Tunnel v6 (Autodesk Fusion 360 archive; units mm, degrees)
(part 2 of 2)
sketch "Sketch9" plane through (70, 0, 0) normal (1, 0, 0) x axis (0, 0, -1)
  line L1 (-4, 58) -> (-4, 62.9289)
  line L2 (-21, 58) -> (-4, 58)
  line L3 (-21, 62.9289) -> (-21, 58)
  line L4 (-25, 62.9289) -> (-21, 62.9289)
  line L5 (-25, 42.9289) -> (-25, 62.9289)
  line L6 (0, 42.9289) -> (-25, 42.9289)
  line L7 (0, 62.9289) -> (0, 42.9289)
  line L8 (-4, 62.9289) -> (0, 62.9289)
  line L9 (-4.1384, 55.5) -> (-21.17, 55.5)
  line L10 (-4.1384, 39.5) -> (-4.1384, 55.5)
  line L11 (-21.17, 39.5) -> (-4.1384, 39.5)
  line L12 (-21.17, 55.5) -> (-21.17, 39.5)
  line L13 (-34.0895, 0) -> (0, 0)
  line L14 (-39.8928, 0) -> (0, 0)
  line L15 (-4.1384, -55.5) -> (-21.17, -55.5)
  line L16 (-4.1384, -39.5) -> (-4.1384, -55.5)
  line L17 (-21.17, -55.5) -> (-21.17, -39.5)
  line L18 (-21.17, -39.5) -> (-4.1384, -39.5)
  point P1 (0, 0)
  point P16 (0, 0)
  point P10 (-21.17, 55.5)
  point P18 (-21.17, -55.5)
  point P11 (-4.1384, 55.5)
  point P19 (-4.1384, -55.5)
  point P12 (-4.1384, 39.5)
  point P20 (-4.1384, -39.5)
  point P13 (-21.17, 39.5)
  point P21 (-21.17, -39.5)
  horizontal L9
  vertical L10
  horizontal L11
  vertical L12
  coincident P1 P16
  parallel L13 L14
  symmetric P10 L14 P18
  symmetric P11 L14 P19
  symmetric P12 L14 P20
  symmetric P13 L14 P21
  dimension "d42" distance L2 L9 = 2.5
  dimension "d43" distance P10 P13 = 16
  dimension "d44" distance L11 L13 = 39.5
extrude "Extrude9" cut sketch "Sketch9" profile of L6 L9 L10 L11 L12 L15 L16 L17 L18 against normal blind 15
sketch "Sketch10" plane through (0, 0, 0) normal (0, 0, -1) x axis (-1, 0, 0)
  line L1 (-65, -40.0422) -> (-70, -28.9289)
  line L2 (-70, -42.9289) -> (-65, -40.0422)
  line L3 (-70, -62.9289) -> (-70, -42.9289)
  line L4 (-62.9289, -70) -> (-70, -62.9289)
  line L5 (-42.9289, -70) -> (-62.9289, -70)
  line L6 (-40.0422, -65) -> (-42.9289, -70)
  line L7 (-28.9289, -70) -> (-40.0422, -65)
  line L8 (28.9289, -70) -> (-28.9289, -70)
  line L9 (40.0422, -65) -> (28.9289, -70)
  line L10 (42.9289, -70) -> (40.0422, -65)
  line L11 (62.9289, -70) -> (42.9289, -70)
  line L12 (70, -62.9289) -> (62.9289, -70)
  line L13 (70, -42.9289) -> (70, -62.9289)
  line L14 (65, -40.0422) -> (70, -42.9289)
  line L15 (70, -28.9289) -> (65, -40.0422)
  line L16 (70, 28.9289) -> (70, -28.9289)
  line L17 (65, 40.0422) -> (70, 28.9289)
  line L18 (70, 42.9289) -> (65, 40.0422)
  line L19 (70, 62.9289) -> (70, 42.9289)
  line L20 (62.9289, 70) -> (70, 62.9289)
  line L21 (42.9289, 70) -> (62.9289, 70)
  line L22 (40.0422, 65) -> (42.9289, 70)
  line L23 (28.9289, 70) -> (40.0422, 65)
  line L24 (-28.9289, 70) -> (28.9289, 70)
  line L25 (-40.0422, 65) -> (-28.9289, 70)
  line L26 (-42.9289, 70) -> (-40.0422, 65)
  line L27 (-62.9289, 70) -> (-42.9289, 70)
  line L28 (-70, 62.9289) -> (-62.9289, 70)
  line L29 (-70, 42.9289) -> (-70, 62.9289)
  line L30 (-65, 40.0422) -> (-70, 42.9289)
  line L31 (-70, 28.9289) -> (-65, 40.0422)
  line L32 (-70, -28.9289) -> (-70, 28.9289)
  line L33 (66.4645, 66.4645) -> (0, 0)
  line L34 (0, 0) -> (-66.4645, 66.4645)
  line L35 (-44.063, 51.1341) -> (-10.8867, 17.9577)
  line L36 (-51.1341, 44.063) -> (-17.9577, 10.8867)
  line L37 (-52.5483, 45.4773) -> (-51.1341, 44.063)
  line L38 (-45.4773, 52.5483) -> (-52.5483, 45.4773)
  line L39 (-44.063, 51.1341) -> (-45.4773, 52.5483)
  line L40 (-51.1341, -44.063) -> (-17.9577, -10.8867)
  line L41 (-44.063, -51.1341) -> (-10.8867, -17.9577)
  line L42 (-52.5483, -45.4773) -> (-45.4773, -52.5483)
  line L43 (-51.1341, -44.063) -> (-52.5483, -45.4773)
  line L44 (-45.4773, -52.5483) -> (-44.063, -51.1341)
  line L45 (44.063, -51.1341) -> (10.8867, -17.9577)
  line L46 (51.1341, -44.063) -> (17.9577, -10.8867)
  line L47 (45.4773, -52.5483) -> (52.5483, -45.4773)
  line L48 (44.063, -51.1341) -> (45.4773, -52.5483)
  line L49 (52.5483, -45.4773) -> (51.1341, -44.063)
  line L50 (51.1341, 44.063) -> (17.9577, 10.8867)
  line L51 (44.063, 51.1341) -> (10.8867, 17.9577)
  line L52 (52.5483, 45.4773) -> (45.4773, 52.5483)
  line L53 (51.1341, 44.063) -> (52.5483, 45.4773)
  line L54 (45.4773, 52.5483) -> (44.063, 51.1341)
  circle C1 centre (-61.8683, 61.8683) radius 2.5
  circle C2 centre (61.8683, -61.8683) radius 2.5
  circle C3 centre (61.8683, 61.8683) radius 2.5
  circle C4 centre (-61.8683, -61.8683) radius 2.5
  circle C5 centre (0, 0) radius 67.5
  arc A1 centre (0, 0) radius 21 clockwise from (-10.8867, 17.9577) to (10.8867, 17.9577)
  arc A2 centre (0, 0) radius 21 clockwise from (-17.9577, -10.8867) to (-17.9577, 10.8867)
  arc A3 centre (0, 0) radius 21 clockwise from (10.8867, -17.9577) to (-10.8867, -17.9577)
  arc A4 centre (0, 0) radius 21 clockwise from (17.9577, 10.8867) to (17.9577, -10.8867)
  point P1 (0, 0)
  point P40 (0, 0)
  point P41 (66.4645, 66.4645)
  point P42 (-66.4645, 66.4645)
  point P44 (-44.063, 51.1341)
  point P46 (-51.1341, 44.063)
  point P47 (-52.5483, 45.4773)
  point P48 (-45.4773, 52.5483)
  concentric C5 A2
  coincident P1 P40
  midpoint L20 P41
  midpoint L28 P42
  coincident C5 P44
  perpendicular L33 L35
  coincident C5 P46
  parallel L34 L36
  symmetric L34 L35 L36
  parallel L36 L37
  perpendicular L34 L38
  concentric A1 A2
  concentric A2 A3
  concentric A3 A4
  dimension "d47" diameter A2 = 42
  dimension "d48" distance L35 L36 = 10
  dimension "d49" distance P47 P48 = 10
  dimension "d50" distance P44 P48 = 2
  dimension "d52" C-Pattern1-Angle = 360
extrude "Extrude10" add sketch "Sketch10" profile of C5 A4 L35 L36 L37 L38 L39 L40 L41 L42 L43 L44 L45 L46 L47 L48 L49 L50 L51 L52 L53 L54 against normal blind 3
fillet "Fillet1" radius 4
chamfer "Chamfer1" distance 3 distance 3 distance 3 distance 3
fillet "Fillet2" radius 1
fillet "Fillet3" radius 1.5
sketch "Sketch11" plane through (0, 0, 0) normal (0, 0, -1) x axis (-1, 0, 0)
  line L1 (-28.9289, 70) -> (-8.3815, 70)
  line L2 (-40.0422, 65) -> (-28.9289, 70)
  line L3 (-42.9289, 70) -> (-40.0422, 65)
  line L4 (-62.9289, 70) -> (-42.9289, 70)
  line L5 (-70, 62.9289) -> (-62.9289, 70)
  line L6 (-70, 42.9289) -> (-70, 62.9289)
  line L7 (-65, 40.0422) -> (-70, 42.9289)
  line L8 (-70, 28.9289) -> (-65, 40.0422)
  line L9 (-70, 8.3815) -> (-70, 28.9289)
  line L10 (-17.1164, 12.1667) -> (-52.2644, 47.3147)
  line L11 (-52.2644, -47.3147) -> (-17.1164, -12.1667)
  line L12 (-70, -28.9289) -> (-70, -8.3815)
  line L13 (-65, -40.0422) -> (-70, -28.9289)
  line L14 (-70, -42.9289) -> (-65, -40.0422)
  line L15 (-70, -62.9289) -> (-70, -42.9289)
  line L16 (-62.9289, -70) -> (-70, -62.9289)
  line L17 (-42.9289, -70) -> (-62.9289, -70)
  line L18 (-40.0422, -65) -> (-42.9289, -70)
  line L19 (-28.9289, -70) -> (-40.0422, -65)
  line L20 (-8.3815, -70) -> (-28.9289, -70)
  line L21 (-12.1667, -17.1164) -> (-47.3147, -52.2644)
  line L22 (47.3147, -52.2644) -> (12.1667, -17.1164)
  line L23 (28.9289, -70) -> (8.3815, -70)
  line L24 (40.0422, -65) -> (28.9289, -70)
  line L25 (42.9289, -70) -> (40.0422, -65)
  line L26 (62.9289, -70) -> (42.9289, -70)
  line L27 (70, -62.9289) -> (62.9289, -70)
  line L28 (70, -42.9289) -> (70, -62.9289)
  line L29 (65, -40.0422) -> (70, -42.9289)
  line L30 (70, -28.9289) -> (65, -40.0422)
  line L31 (70, -8.3815) -> (70, -28.9289)
  line L32 (17.1164, -12.1667) -> (52.2644, -47.3147)
  line L33 (52.2644, 47.3147) -> (17.1164, 12.1667)
  line L34 (70, 28.9289) -> (70, 8.3815)
  line L35 (65, 40.0422) -> (70, 28.9289)
  line L36 (70, 42.9289) -> (65, 40.0422)
  line L37 (70, 62.9289) -> (70, 42.9289)
  line L38 (62.9289, 70) -> (70, 62.9289)
  line L39 (42.9289, 70) -> (62.9289, 70)
  line L40 (40.0422, 65) -> (42.9289, 70)
  line L41 (28.9289, 70) -> (40.0422, 65)
  line L42 (8.3815, 70) -> (28.9289, 70)
  line L43 (12.1667, 17.1164) -> (47.3147, 52.2644)
  line L44 (-47.3147, 52.2644) -> (-12.1667, 17.1164)
  line L45 (-51.4652, 51.4652) -> (0, 0)
  line L46 (-47.5719, 50.4004) -> (-50.4004, 47.5719)
  line L47 (-13.6308, 16.4592) -> (-47.5719, 50.4004)
  line L48 (-16.4592, 13.6308) -> (-13.6308, 16.4592)
  line L49 (-50.4004, 47.5719) -> (-16.4592, 13.6308)
  line L50 (-16.4592, -13.6308) -> (-50.4004, -47.5719)
  line L51 (-47.5719, -50.4004) -> (-13.6308, -16.4592)
  line L52 (-50.4004, -47.5719) -> (-47.5719, -50.4004)
  line L53 (-13.6308, -16.4592) -> (-16.4592, -13.6308)
  line L54 (13.6308, -16.4592) -> (47.5719, -50.4004)
  line L55 (50.4004, -47.5719) -> (16.4592, -13.6308)
  line L56 (47.5719, -50.4004) -> (50.4004, -47.5719)
  line L57 (16.4592, -13.6308) -> (13.6308, -16.4592)
  line L58 (16.4592, 13.6308) -> (50.4004, 47.5719)
  line L59 (47.5719, 50.4004) -> (13.6308, 16.4592)
  line L60 (50.4004, 47.5719) -> (47.5719, 50.4004)
  line L61 (13.6308, 16.4592) -> (16.4592, 13.6308)
  arc A1 centre (0, 0) radius 70.5 clockwise from (-47.3147, 52.2644) to (-8.3815, 70)
  arc A2 centre (0, 0) radius 70.5 clockwise from (-70, 8.3815) to (-52.2644, 47.3147)
  arc A3 centre (0, 0) radius 21 clockwise from (-17.1164, -12.1667) to (-17.1164, 12.1667)
  arc A4 centre (0, 0) radius 70.5 clockwise from (-52.2644, -47.3147) to (-70, -8.3815)
  arc A5 centre (0, 0) radius 70.5 clockwise from (-8.3815, -70) to (-47.3147, -52.2644)
  arc A6 centre (0, 0) radius 21 clockwise from (12.1667, -17.1164) to (-12.1667, -17.1164)
  arc A7 centre (0, 0) radius 70.5 clockwise from (47.3147, -52.2644) to (8.3815, -70)
  arc A8 centre (0, 0) radius 70.5 clockwise from (70, -8.3815) to (52.2644, -47.3147)
  arc A9 centre (0, 0) radius 21 clockwise from (17.1164, 12.1667) to (17.1164, -12.1667)
  arc A10 centre (0, 0) radius 70.5 clockwise from (52.2644, 47.3147) to (70, 8.3815)
  arc A11 centre (0, 0) radius 70.5 clockwise from (8.3815, 70) to (47.3147, 52.2644)
  arc A12 centre (0, 0) radius 21 clockwise from (-12.1667, 17.1164) to (12.1667, 17.1164)
  circle C1 centre (-61.8683, -61.8683) radius 2.5
  circle C2 centre (61.8683, 61.8683) radius 2.5
  circle C3 centre (61.8683, -61.8683) radius 2.5
  circle C4 centre (-61.8683, 61.8683) radius 2.5
  point P4 (0, 0)
  point P63 (0, 0)
  point P66 (-47.5719, 50.4004)
  point P67 (-13.6308, 16.4592)
  coincident P4 P63
  parallel L44 L45
  perpendicular L45 L46
  perpendicular L46 L47
  perpendicular L10 L48
  parallel L47 L49
  dimension "d65" distance L47 L49 = 4
  dimension "d66" distance P66 P67 = 48
  dimension "d67" distance L45 L47 = 2
  dimension "d69" C-Pattern1-Angle = 360
extrude "Extrude11" cut sketch "Sketch11" profile of L46 L47 L48 L49 L50 L51 L52 L53 L54 L55 L56 L57 L58 L59 L60 L61 against normal blind 2
sketch "Sketch12" plane through (0, 70, 0) normal (0, 1, 0) x axis (-1, 0, 0)
  line L1 (62.9289, 21) -> (55, 21)
  line L2 (62.9289, 25) -> (62.9289, 21)
  line L3 (42.9289, 25) -> (62.9289, 25)
  line L4 (42.9289, 0) -> (42.9289, 25)
  line L5 (62.9289, 0) -> (42.9289, 0)
  line L6 (62.9289, 4) -> (62.9289, 0)
  line L7 (55, 4) -> (62.9289, 4)
  line L8 (55, 21) -> (55, 4)
  line L9 (0, 12.5) -> (55, 12.5)
  line L10 (37, 4.5) -> (53, 4.5)
  line L11 (37, 20.5) -> (37, 4.5)
  line L12 (53, 20.5) -> (37, 20.5)
  line L13 (53, 4.5) -> (53, 20.5)
  line L14 (0, 34.7836) -> (0, 0)
  line L15 (0, 34.7836) -> (0, 0)
  line L16 (-37, 4.5) -> (-53, 4.5)
  line L17 (-53, 4.5) -> (-53, 20.5)
  line L18 (-53, 20.5) -> (-37, 20.5)
  line L19 (-37, 20.5) -> (-37, 4.5)
  point P10 (55, 12.5)
  point P1 (0, 0)
  point P16 (0, 0)
  point P12 (53, 4.5)
  point P20 (-53, 4.5)
  point P13 (37, 4.5)
  point P21 (-37, 4.5)
  point P14 (37, 20.5)
  point P23 (-37, 20.5)
  point P15 (53, 20.5)
  point P22 (-53, 20.5)
  point P18 (0, 0)
  point P17 (0, 34.7836)
  point P19 (0, 34.7836)
  midpoint L8 P10
  perpendicular L8 L9
  horizontal L10
  vertical L11
  horizontal L12
  vertical L13
  symmetric L9 L10 L12
  coincident P1 P16
  perpendicular L10 L14
  symmetric P12 L14 P20
  symmetric P13 L14 P21
  symmetric P14 L14 P23
  symmetric P15 L14 P22
  symmetric P16 L14 P18
  symmetric P17 L14 P19
  dimension "d72" distance L8 L13 = 2
  dimension "d73" distance L11 L13 = 16
  dimension "d74" distance L10 L12 = 16
extrude "Extrude12" cut sketch "Sketch12" profile of L4 L10 L11 L12 L13 L16 L17 L18 L19 against normal blind 12
sketch "Sketch13" plane through (0, -70, 0) normal (0, -1, 0) x axis (1, 0, 0)
  line L1 (-62.9289, 4) -> (-55, 4)
  line L2 (-62.9289, 0) -> (-62.9289, 4)
  line L3 (-42.9289, 0) -> (-62.9289, 0)
  line L4 (-42.9289, 25) -> (-42.9289, 0)
  line L5 (-62.9289, 25) -> (-42.9289, 25)
  line L6 (-62.9289, 21) -> (-62.9289, 25)
  line L7 (-55, 21) -> (-62.9289, 21)
  line L8 (-55, 4) -> (-55, 21)
  line L9 (0.7063, 12.5) -> (-42.9289, 12.5)
  line L10 (-37, 20.5) -> (-53, 20.5)
  line L11 (-37, 4.5) -> (-37, 20.5)
  line L12 (-53, 4.5) -> (-37, 4.5)
  line L13 (-53, 20.5) -> (-53, 4.5)
  line L14 (0, 32.9134) -> (0, 0)
  line L15 (53, 20.5) -> (53, 4.5)
  line L16 (37, 20.5) -> (53, 20.5)
  line L17 (53, 4.5) -> (37, 4.5)
  line L18 (37, 4.5) -> (37, 20.5)
  point P10 (-42.9289, 12.5)
  point P1 (0, 0)
  point P16 (0, 0)
  point P12 (-53, 20.5)
  point P19 (53, 20.5)
  point P13 (-37, 20.5)
  point P20 (37, 20.5)
  point P14 (-37, 4.5)
  point P21 (37, 4.5)
  point P15 (-53, 4.5)
  point P18 (53, 4.5)
  midpoint L4 P10
  perpendicular L4 L9
  horizontal L10
  vertical L11
  horizontal L12
  vertical L13
  symmetric L9 L10 L12
  coincident P1 P16
  vertical L14
  symmetric P12 L14 P19
  symmetric P13 L14 P20
  symmetric P14 L14 P21
  symmetric P15 L14 P18
  dimension "d77" distance L8 L13 = 2
  dimension "d78" distance L11 L13 = 16
  dimension "d79" distance L10 L12 = 16
extrude "Extrude13" cut sketch "Sketch13" profile of L4 L10 L11 L12 L13 L15 L16 L17 L18 against normal blind 10
chamfer "Chamfer2" distance 2 distance 2 distance 2
chamfer "Chamfer3" distance 2
chamfer "Chamfer4" distance 2
chamfer "Chamfer5" distance 2
chamfer "Chamfer6" distance 2
sketch "Sketch14" plane through (0, 0, 3) normal (0, 0, 1) x axis (1, 0, 0)
  line L1 (11.749, 17.4058) -> (44.8174, 50.4743)
  line L2 (-44.8174, 50.4743) -> (-11.749, 17.4058)
  line L3 (-17.4058, 11.749) -> (-50.4743, 44.8174)
  line L4 (-50.4743, -44.8174) -> (-17.4058, -11.749)
  line L5 (-11.749, -17.4058) -> (-44.8174, -50.4743)
  line L6 (44.8174, -50.4743) -> (11.749, -17.4058)
  line L7 (17.4058, -11.749) -> (50.4743, -44.8174)
  line L8 (50.4743, 44.8174) -> (17.4058, 11.749)
  arc A1 centre (0, 0) radius 21 clockwise from (-11.749, 17.4058) to (11.749, 17.4058)
  arc A2 centre (0, 0) radius 67.5 clockwise from (-50.4743, 44.8174) to (-44.8174, 50.4743)
  arc A3 centre (0, 0) radius 21 clockwise from (-17.4058, -11.749) to (-17.4058, 11.749)
  arc A4 centre (0, 0) radius 67.5 clockwise from (-44.8174, -50.4743) to (-50.4743, -44.8174)
  arc A5 centre (0, 0) radius 21 clockwise from (11.749, -17.4058) to (-11.749, -17.4058)
  arc A6 centre (0, 0) radius 67.5 clockwise from (50.4743, -44.8174) to (44.8174, -50.4743)
  arc A7 centre (0, 0) radius 21 clockwise from (17.4058, 11.749) to (17.4058, -11.749)
  arc A8 centre (0, 0) radius 67.5 clockwise from (44.8174, 50.4743) to (50.4743, 44.8174)

design "LRS-35-12"
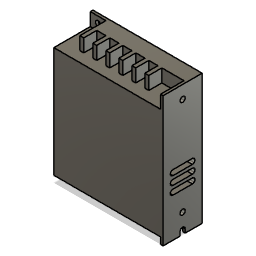
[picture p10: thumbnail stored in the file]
sketch "Sketch1" plane through (0, 0, 0) normal (0, 0, 1) x axis (1, 0, 0)
  line L1 (2, 0) -> (0, 0)
  line L2 (2, 100) -> (2, 0)
  line L3 (0, 100) -> (2, 100)
  line L4 (0, 0) -> (0, 100)
  point P1 (0, 0)
  point P2 (0, 0)
  point P3 (2, 0)
  point P5 (0, 100)
  horizontal L1
  vertical L2
  horizontal L3
  vertical L4
  coincident P1 P2
  dimension "d1" distance P2 P3 = 2
  dimension "d2" distance P2 P5 = 100
extrude "Extrude1" new body sketch "Sketch1" along normal blind 30
sketch "Sketch2" plane through (0, 0, 0) normal (0, 0, 1) x axis (1, 0, 0)
  line L1 (-82, 0) -> (0, 0)
  line L2 (-82, 100) -> (-82, 0)
  line L3 (0, 100) -> (-82, 100)
  line L4 (0, 0) -> (0, 100)
  point P1 (0, 0)
  point P2 (0, 0)
  point P5 (0, 100)
  point P3 (-82, 0)
  horizontal L1
  vertical L2
  horizontal L3
  vertical L4
  coincident P1 P2
  dimension "d5" distance P2 P5 = 100
  dimension "d6" distance P2 P3 = 82
extrude "Extrude2" add sketch "Sketch2" along normal blind 2
sketch "Sketch3" plane through (0, 0, 2) normal (0, 0, 1) x axis (1, 0, 0)
  line L1 (-82, 100) -> (0, 100)
  line L2 (-82, 0) -> (-82, 100)
  line L3 (0, 0) -> (-82, 0)
  line L4 (0, 100) -> (0, 0)
  line L5 (-82, 5) -> (0, 5)
  line L6 (-82, 90) -> (-82, 5)
  line L7 (0, 90) -> (-82, 90)
  line L8 (0, 5) -> (0, 90)
  point P6 (0, 5)
  point P8 (-82, 90)
  horizontal L5
  vertical L6
  horizontal L7
  vertical L8
  coincident L4 P6
  coincident L2 P8
  dimension "d9" distance L3 L5 = 5
  dimension "d10" distance L1 L7 = 10
extrude "Extrude3" add sketch "Sketch3" profile of L2 L4 L5 L6 L7 L8 along normal blind 28
sketch "Sketch4" plane through (0, 0, 2) normal (0, 0, 1) x axis (1, 0, 0)
  line L1 (0, 90) -> (-82, 90)
  line L2 (0, 100) -> (0, 90)
  line L3 (-82, 100) -> (0, 100)
  line L4 (-82, 90) -> (-82, 100)
  line L5 (0, 100) -> (-70, 100)
  line L6 (0, 90) -> (0, 100)
  line L7 (-70, 90) -> (0, 90)
  line L8 (-70, 100) -> (-70, 90)
  point P3 (0, 90)
  point P8 (0, 90)
  point P6 (-70, 100)
  point P7 (0, 100)
  horizontal L5
  vertical L6
  horizontal L7
  vertical L8
  coincident P3 P8
  coincident L3 P6
  dimension "d13" distance P6 P7 = 70
extrude "Extrude4" add sketch "Sketch4" profile of L1 L2 L3 L5 L6 L7 L8 along normal blind 20
sketch "Sketch5" plane through (0, 0, 22) normal (0, 0, 1) x axis (1, 0, 0)
  line L1 (0, 90) -> (-70, 90)
  line L2 (0, 100) -> (0, 90)
  line L3 (-70, 100) -> (0, 100)
  line L4 (-70, 90) -> (-70, 100)
  line L5 (-60, 100) -> (-67, 100)
  line L6 (-60, 90) -> (-60, 100)
  line L7 (-67, 90) -> (-60, 90)
  line L8 (-67, 100) -> (-67, 90)
  line L9 (-17, 103.9191) -> (-17, 90)
  line L10 (-57, 100) -> (-57, 90)
  line L11 (-50, 100) -> (-57, 100)
  line L12 (-50, 90) -> (-50, 100)
  line L13 (-57, 90) -> (-50, 90)
  line L14 (-47, 100) -> (-47, 90)
  line L15 (-40, 100) -> (-47, 100)
  line L16 (-40, 90) -> (-40, 100)
  line L17 (-47, 90) -> (-40, 90)
  line L18 (-37, 100) -> (-37, 90)
  line L19 (-30, 100) -> (-37, 100)
  line L20 (-30, 90) -> (-30, 100)
  line L21 (-37, 90) -> (-30, 90)
  line L22 (-27, 100) -> (-27, 90)
  line L23 (-20, 100) -> (-27, 100)
  line L24 (-20, 90) -> (-20, 100)
  line L25 (-27, 90) -> (-20, 90)
  line L26 (0, 100) -> (-17, 100)
  line L27 (0, 90) -> (0, 100)
  line L28 (-17, 90) -> (0, 90)
  line L29 (-17, 100) -> (-17, 90)
  point P8 (-60, 90)
  point P6 (-67, 100)
  point P10 (-17, 90)
  point P3 (0, 90)
  point P30 (0, 90)
  point P28 (-17, 100)
  point P7 (-60, 100)
  horizontal L5
  vertical L6
  horizontal L7
  vertical L8
  coincident L1 P8
  coincident L3 P6
  coincident L1 P10
  perpendicular L3 L9
  horizontal L26
  vertical L27
  horizontal L28
  vertical L29
  coincident P3 P30
  coincident L9 P28
  coincident L3 P28
  dimension "d16" distance L4 L8 = 3
  dimension "d17" distance P6 P7 = 7
  dimension "d18" distance P6 L9 = 50
  dimension "d21" R-Pattern1-uDistance = 40
  dimension "d22" R-Pattern1-vDistance = 0
extrude "Extrude5" cut sketch "Sketch5" profile of L1 L2 L3 L5 L6 L7 L8 L10 L11 L12 L13 L14 L15 L16 L17 L18 L19 L20 L21 L22 L23 L24 L25 L26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 against normal blind 10
sketch "Sketch6" plane through (0, 0, 2) normal (0, 0, 1) x axis (1, 0, 0)
  line L1 (-70, 100) -> (-70, 90)
  line L2 (-82, 100) -> (-70, 100)
  line L3 (-82, 90) -> (-82, 100)
  line L4 (-70, 90) -> (-82, 90)
  circle C1 centre (-76, 95) radius 2
  point P6 (-76, 95)
  dimension "d25" diameter C1 = 4
  dimension "d26" distance L2 P6 = 5
  dimension "d27" distance L3 P6 = 6
extrude "Extrude6" cut sketch "Sketch6" profile of C1 against normal blind 9
sketch "Sketch7" plane through (2, 0, 0) normal (1, 0, 0) x axis (0, 0, -1)
  line L1 (0, 100) -> (0, 0)
  line L2 (-30, 100) -> (0, 100)
  line L3 (-30, 0) -> (-30, 100)
  line L4 (0, 0) -> (-30, 0)
  line L5 (-15, 100) -> (-15, 0)
  line L6 (-13, 3) -> (-13, 0)
  line L7 (-17, 0) -> (-17, 3)
  line L8 (-15, 3) -> (-15, -3)
  line L9 (-13, 0) -> (-17, 0)
  arc A1 centre (-15, 3) radius 2 clockwise from (-17, 3) to (-13, 3)
  point P6 (-15, 0)
  point P7 (-15, 100)
  point P11 (-15, 3)
  point P12 (-15, 0)
  midpoint L4 P6
  midpoint L2 P7
  tangent L6 A1
  tangent A1 L7
  parallel L6 L7
  coincident L5 P11
  parallel L5 L8
  coincident P6 P12
  midpoint L8 P12
  dimension "d30" distance P11 P12 = 3
  dimension "d31" diameter A1 = 4
extrude "Extrude7" cut sketch "Sketch7" profile of L4 L6 A1 L7 L9 against normal blind 2
sketch "Sketch8" plane through (2, 0, 0) normal (1, 0, 0) x axis (0, 0, -1)
  line L1 (-17, 3) -> (-17, 0)
  line L2 (-13, 0) -> (-13, 3)
  line L3 (0, 0) -> (-13, 0)
  line L4 (0, 100) -> (0, 0)
  line L5 (-30, 100) -> (0, 100)
  line L6 (-30, 0) -> (-30, 100)
  line L7 (-17, 0) -> (-30, 0)
  line L8 (-15, 100) -> (-15, 5)
  line L9 (-22.5, 34) -> (-7.5, 34)
  line L10 (-7.5, 30) -> (-22.5, 30)
  line L11 (-22.5, 32) -> (-7.5, 32)
  line L12 (-22.5, 40.5) -> (-7.5, 40.5)
  line L13 (-7.5, 36.5) -> (-22.5, 36.5)
  line L14 (-22.5, 47) -> (-7.5, 47)
  line L15 (-7.5, 43) -> (-22.5, 43)
  arc A1 centre (-15, 3) radius 2 clockwise from (-17, 3) to (-13, 3)
  circle C1 centre (-15, 15) radius 2
  circle C2 centre (-15, 90) radius 2
  arc A2 centre (-22.5, 32) radius 2 clockwise from (-22.5, 30) to (-22.5, 34)
  arc A3 centre (-7.5, 32) radius 2 clockwise from (-7.5, 34) to (-7.5, 30)
  arc A4 centre (-22.5, 38.5) radius 2 clockwise from (-22.5, 36.5) to (-22.5, 40.5)
  arc A5 centre (-7.5, 38.5) radius 2 clockwise from (-7.5, 40.5) to (-7.5, 36.5)
  arc A6 centre (-22.5, 45) radius 2 clockwise from (-22.5, 43) to (-22.5, 47)
  arc A7 centre (-7.5, 45) radius 2 clockwise from (-7.5, 47) to (-7.5, 43)
  point P11 (-15, 5)
  point P12 (-15, 100)
  point P13 (-15, 15)
  point P14 (-15, 90)
  point P21 (-15, 32)
  point P2 (-17, 0)
  midpoint A1 P11
  midpoint L5 P12
  coincident L8 P13
  coincident L8 P14
  tangent L9 A2
  tangent A2 L10
  parallel L9 L10
  tangent L10 A3
  tangent L9 A3
  perpendicular L8 L11
  coincident L8 P21
  midpoint L11 P21
  dimension "d34" diameter C1 = 4
  dimension "d35" diameter C2 = 4
  dimension "d36" distance L7 P13 = 15
  dimension "d37" distance L5 P14 = 10
  dimension "d38" diameter A2 = 4
  dimension "d39" distance P2 P21 = 32
  dimension "d42" R-Pattern1-uDistance = 0
  dimension "d43" R-Pattern1-vDistance = 13
extrude "Extrude8" cut sketch "Sketch8" profile of A1 C1 C2 L9 A2 L10 A3 L12 A4 L13 A5 L14 A6 L15 A7 against normal blind 4

design "Air_out_Strainer"
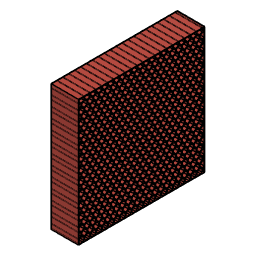
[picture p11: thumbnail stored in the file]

design "Testing section"
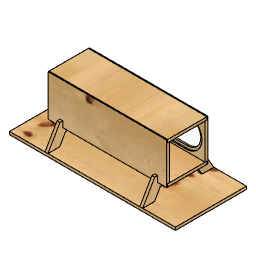
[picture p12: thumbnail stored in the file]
sketch "Front" plane through (0, 0, 0) normal (0, 0, 1) x axis (1, 0, 0)
  line L1 (500, 0) -> (0, 0)
  line L2 (500, 174) -> (500, 0)
  line L3 (0, 174) -> (500, 174)
  line L4 (0, 0) -> (0, 174)
  line L5 (500, 87) -> (0, 87)
  line L6 (420, 30) -> (80, 30)
  line L7 (80, 144) -> (420, 144)
  line L8 (420, 87) -> (80, 87)
  arc A1 centre (420, 87) radius 57 clockwise from (420, 144) to (420, 30)
  arc A2 centre (80, 87) radius 57 clockwise from (80, 30) to (80, 144)
  point P1 (0, 0)
  point P2 (0, 0)
  point P6 (0, 87)
  point P7 (500, 87)
  point P13 (420, 87)
  point P3 (500, 0)
  point P5 (0, 174)
  point P12 (80, 87)
  horizontal L1
  vertical L2
  horizontal L3
  vertical L4
  coincident P1 P2
  midpoint L4 P6
  midpoint L2 P7
  tangent L6 A1
  tangent A1 L7
  parallel L6 L7
  tangent L7 A2
  tangent L6 A2
  coincident L5 P13
  parallel L5 L8
  dimension "d1" distance P2 P3 = 500
  dimension "d2" distance P2 P5 = 174
  dimension "d3" distance P6 P12 = 80
  dimension "d4" distance L2 P13 = 80
  dimension "d5" distance L3 L7 = 30
  dimension "d6" radius A2 = 57
  dimension "d7" distance P12 P13 = 340
extrude "Extrude1" new body sketch "Front" profile of L1 L2 L3 L4 L6 A1 L7 A2 along normal blind 12 bodies "Front"
sketch "front noching" plane through (0, 0, 12) normal (0, 0, 1) x axis (1, 0, 0)
  line L1 (420, 144) -> (80, 144)
  line L2 (80, 30) -> (420, 30)
  line L3 (0, 0) -> (0, 174)
  line L4 (500, 0) -> (0, 0)
  line L5 (500, 174) -> (500, 0)
  line L6 (0, 174) -> (500, 174)
  line L7 (500, 174) -> (0, 174)
  line L8 (500, 162) -> (500, 174)
  line L9 (0, 162) -> (500, 162)
  line L10 (0, 174) -> (0, 162)
  line L11 (500, 87) -> (0, 87)
  line L12 (500, 0) -> (0, 0)
  line L13 (500, 12) -> (500, 0)
  line L14 (0, 12) -> (500, 12)
  line L15 (0, 0) -> (0, 12)
  line L16 (420.1, 20) -> (79.9, 20)
  line L17 (79.9, 154) -> (420.1, 154)
  line L18 (420.1, 87) -> (79.9, 87)
  arc A1 centre (80, 87) radius 57 clockwise from (80, 30) to (80, 144)
  arc A2 centre (420, 87) radius 57 clockwise from (420, 144) to (420, 30)
  arc A3 centre (420.1, 87) radius 67 clockwise from (420.1, 154) to (420.1, 20)
  arc A4 centre (79.9, 87) radius 67 clockwise from (79.9, 20) to (79.9, 154)
  point P14 (500, 162)
  point P8 (0, 174)
  point P12 (0, 174)
  point P16 (0, 87)
  point P17 (500, 87)
  point P20 (500, 12)
  point P1 (0, 0)
  point P18 (0, 0)
  point P27 (420.1, 87)
  point P4 (80, 87)
  point P26 (79.9, 87)
  point P7 (420, 87)
  horizontal L7
  vertical L8
  horizontal L9
  vertical L10
  coincident L5 P14
  coincident P8 P12
  midpoint L3 P16
  midpoint L5 P17
  horizontal L12
  vertical L13
  horizontal L14
  vertical L15
  coincident L5 P20
  coincident P1 P18
  tangent L16 A3
  tangent A3 L17
  parallel L16 L17
  tangent L17 A4
  tangent L16 A4
  coincident L11 P27
  parallel L11 L18
  dimension "d10" distance L12 L14 = 12
  dimension "d11" distance L7 L9 = 12
  dimension "d12" distance P4 P26 = 0.1
  dimension "d13" distance P7 P27 = 0.1
  dimension "d14" distance L1 L17 = 10
  dimension "d15" distance L2 L16 = 10
extrude "Extrude2" cut sketch "front noching" profile of L3 L4 L5 L6 L7 L8 L9 L10 L12 L13 L14 L15 against normal blind 8
extrude "Extrude3" cut sketch "front noching" profile of A1 L1 A2 L2 L16 A3 L17 A4 against normal blind 5
sketch "Top" plane through (0, 174, 0) normal (0, 1, 0) x axis (-1, 0, 0)
  line L1 (-500, 4) -> (0, 4)
  line L2 (-500, 0) -> (-500, 4)
  line L3 (0, 0) -> (-500, 0)
  line L4 (0, 4) -> (0, 0)
  line L5 (-500, 4) -> (0, 4)
  line L6 (-500, 170) -> (-500, 4)
  line L7 (0, 170) -> (-500, 170)
  line L8 (0, 4) -> (0, 170)
  point P2 (0, 4)
  point P6 (0, 4)
  point P7 (-500, 4)
  point P8 (-500, 170)
  point P9 (0, 170)
  horizontal L5
  vertical L6
  horizontal L7
  vertical L8
  coincident P2 P6
  dimension "d20" distance P7 P8 = 166 (= "150 mm + 16 mm")
  dimension "d21" distance P8 P9 = 500
extrude "Extrude4" new body sketch "Top" profile of L1 L5 L6 L7 L8 against normal blind 12 bodies "Top"
sketch "Bottom" plane through (0, 0, 0) normal (-1, 0, 0) x axis (0, 0, 1)
  line L1 (4, 162) -> (12, 162)
  line L2 (4, 174) -> (4, 162)
  line L3 (0, 174) -> (4, 174)
  line L4 (0, 0) -> (0, 174)
  line L5 (4, 0) -> (0, 0)
  line L6 (4, 12) -> (4, 0)
  line L7 (12, 12) -> (4, 12)
  line L8 (12, 162) -> (12, 12)
  line L9 (170, 0) -> (4, 0)
  line L10 (170, 12) -> (170, 0)
  line L11 (4, 12) -> (170, 12)
  line L12 (4, 0) -> (4, 12)
  point P7 (4, 0)
  point P10 (4, 0)
  point P11 (170, 0)
  horizontal L9
  vertical L10
  horizontal L11
  vertical L12
  coincident P7 P10
  dimension "d24" distance P10 P11 = 166
  dimension "d25" distance L9 L11 = 12
extrude "Extrude5" new body sketch "Bottom" profile of L6 L7 L9 L10 L11 L12 against normal blind 500 bodies "Bottom"
sketch "Back" plane through (0, 0, 0) normal (-1, 0, 0) x axis (0, 0, 1)
  line L1 (4, 174) -> (170, 174)
  line L2 (4, 162) -> (4, 174)
  line L3 (170, 162) -> (4, 162)
  line L4 (170, 174) -> (170, 162)
  line L5 (174, 174) -> (170, 174)
  line L6 (174, 0) -> (174, 174)
  line L7 (170, 0) -> (174, 0)
  line L8 (162, 162) -> (170, 162)
  line L9 (162, 12) -> (162, 162)
  line L10 (170, 12) -> (162, 12)
  line L11 (170, 162) -> (170, 12)
  line L12 (170, 12) -> (170, 0)
  line L13 (170, 174) -> (170, 162)
  point P2 (170, 174)
  point P6 (170, 174)
  point P5 (170, 162)
  point P10 (170, 162)
  point P11 (162, 162)
  point P12 (162, 12)
  horizontal L5
  vertical L6
  horizontal L7
  vertical L12
  coincident P2 P6
  horizontal L8
  vertical L9
  horizontal L10
  vertical L11
  coincident P5 P10
  collinear L12 L13
  dimension "d28" distance L6 L12 = 4
  dimension "d29" distance L6 L9 = 12
  dimension "d30" distance L5 L7 = 174
  dimension "d31" distance P11 P12 = 150
extrude "Extrude6" new body sketch "Back" profile of L3 L4 L5 L6 L7 L13 L8 L9 L10 L11 against normal blind 500 bodies "Back"
sketch "Window" plane through (0, 0, 12) normal (0, 0, 1) x axis (1, 0, 0)
  line L1 (79.9, 20) -> (420.1, 20)
  line L2 (420.1, 154) -> (79.9, 154)
  line L3 (0, 162) -> (500, 162)
  line L4 (0, 12) -> (0, 162)
  line L5 (500, 12) -> (0, 12)
  line L6 (500, 162) -> (500, 12)
  line L7 (487.1, 87) -> (12.9, 87)
  line L8 (79.9, 154) -> (420.1, 154)
  line L9 (420.1, 20) -> (79.9, 20)
  line L10 (12.9, 87) -> (487.1, 87)
  arc A1 centre (79.9, 87) radius 67 clockwise from (79.9, 20) to (79.9, 154)
  arc A2 centre (420.1, 87) radius 67 clockwise from (420.1, 154) to (420.1, 20)
  arc A3 centre (79.9, 87) radius 67 clockwise from (79.9, 20) to (79.9, 154)
  arc A4 centre (420.1, 87) radius 67 clockwise from (420.1, 154) to (420.1, 20)
  point P12 (12.9, 87)
  point P13 (487.1, 87)
  midpoint A1 P12
  midpoint A2 P13
  tangent L8 A3
  tangent A3 L9
  parallel L8 L9
  tangent L9 A4
  tangent L8 A4
  midpoint P13 A4
  midpoint P12 A3
extrude "Extrude7" new body sketch "Window" profile of L1 A1 L2 A2 L8 A3 L9 A4 against normal blind 5 bodies "window"
sketch "Stand Legs" plane through (0, 0, 0) normal (1, 0, 0) x axis (0, 0, -1)
  line L1 (-174, 174) -> (0, 174)
  line L2 (-174, 0) -> (-174, 174)
  line L3 (0, 0) -> (-174, 0)
  line L4 (0, 174) -> (0, 0)
  line L5 (-174, 0) -> (0, 174)
  line L6 (0, 0) -> (-174, 174)
  line L7 (63, 237) -> (-237, 237)
  line L8 (63, -63) -> (63, 237)
  line L9 (-237, -63) -> (63, -63)
  line L10 (-237, 237) -> (-237, -63)
  line L11 (63, -63) -> (-237, 237)
  line L12 (-237, -63) -> (63, 237)
  line L13 (-87, 0) -> (-87, 174)
  line L14 (12, 25.3346) -> (0, 25.3346)
  line L15 (63, -63) -> (12, 25.3346)
  line L16 (13, -63) -> (63, -63)
  line L17 (-11.8261, -20) -> (13, -63)
  line L18 (-87, -64.937) -> (-87, 0)
  line L19 (0, 0) -> (0, 25.3346)
  line L20 (0, 0) -> (-87, 0)
  line L21 (-87, -18.4309) -> (-87, 0)
  line L22 (-87, -20) -> (-11.8261, -20)
  line L23 (-87, -18.4309) -> (-87, 0)
  line L24 (-174, 0) -> (-87, 0)
  line L25 (-186, 25.3346) -> (-174, 25.3346)
  line L26 (-237, -63) -> (-186, 25.3346)
  line L27 (-162.1739, -20) -> (-187, -63)
  line L28 (-87, -20) -> (-162.1739, -20)
  line L29 (-187, -63) -> (-237, -63)
  line L30 (-174, 0) -> (-174, 25.3346)
  line L31 (20.5, -75) -> (20.5, -63)
  line L32 (55.5, -75) -> (20.5, -75)
  line L33 (55.5, -63) -> (55.5, -75)
  line L34 (-194.5, -75) -> (-194.5, -63)
  line L35 (-229.5, -75) -> (-194.5, -75)
  line L36 (-229.5, -63) -> (-229.5, -75)
  point P1 (0, 0)
  point P5 (0, 0)
  point P4 (-174, 0)
  point P6 (-174, 0)
  point P2 (0, 174)
  point P7 (0, 174)
  point P8 (0, 174)
  point P9 (-174, 0)
  point P10 (0, 0)
  point P15 (-87, 87)
  point P16 (-87, 174)
  point P17 (-87, 0)
  point P18 (0, 25.3346)
  point P20 (13, -63)
  point P23 (0, 0)
  point P24 (0, 0)
  point P25 (-87, -18.4309)
  point P13 (63, -63)
  point P32 (-237, -63)
  point P27 (-87, 0)
  point P30 (-174, 25.3346)
  point P19 (12, 25.3346)
  point P31 (-186, 25.3346)
  point P33 (-187, -63)
  point P21 (-11.8261, -20)
  point P34 (-162.1739, -20)
  point P36 (-174, 0)
  point P29 (-174, 0)
  point P28 (-87, -18.4309)
  point P26 (-87, -20)
  point P35 (-87, -20)
  point P37 (55.5, -63)
  point P44 (-229.5, -63)
  point P38 (20.5, -63)
  point P41 (-194.5, -63)
  point P39 (20.5, -75)
  point P42 (-194.5, -75)
  point P40 (55.5, -75)
  point P43 (-229.5, -75)
  point P11 (-237, 237)
  point P12 (63, 237)
  horizontal L1
  vertical L2
  horizontal L3
  vertical L4
  coincident P1 P5
  coincident P4 P6
  coincident P2 P7
  coincident P7 P8
  coincident P6 P9
  coincident P1 P10
  horizontal L7
  perpendicular L7 L8
  parallel L7 L9
  parallel L8 L10
  coincident L11 P15
  coincident L12 P15
  midpoint L6 P15
  midpoint L1 P16
  midpoint L3 P17
  coincident L4 P18
  perpendicular L4 L14
  coincident L9 P20
  perpendicular L3 L18
  coincident P1 P23
  coincident P1 P24
  coincident L18 P25
  perpendicular L18 L22
  parallel L15 L17
  symmetric P13 L18 P32
  symmetric P17 L18 P27
  symmetric P18 L18 P30
  symmetric P19 L18 P31
  symmetric P20 L18 P33
  symmetric P21 L18 P34
  symmetric L18 P23 P36
  symmetric L18 P24 P29
  symmetric L18 P25 P28
  symmetric L18 P26 P35
  vertical L31
  horizontal L32
  vertical L33
  coincident L16 P37
  symmetric L18 P37 P44
  symmetric L18 P38 P41
  symmetric L18 P39 P42
  symmetric L18 P40 P43
  dimension "d36" distance P11 P12 = 300
  dimension "d37" distance P12 P13 = 300
  dimension "d38" distance P18 P19 = 12
  dimension "d39" angle L15 L16 = 60
  dimension "d40" distance L3 L22 = 20
  dimension "d41" distance P20 P21 = 43
  dimension "d42" angle L17 L22 = 120
  dimension "d43" distance P13 P20 = 50
  dimension "d46" distance P37 P40 = 12
  dimension "d47" distance P39 P40 = 35
  dimension "d48" distance P13 L33 = 7.5
extrude "Extrude8" new body sketch "Stand Legs" profile of L14 L15 L16 L17 L19 L20 L22 L24 L25 L26 L27 L28 L29 L30 along normal blind 12 bodies "Stand legs1"
move "Move1"
copy_paste_bodies "CopyPasteBodies1"
move "Move2"
sketch "finger joint" plane through (50, 0, 0) normal (-1, 0, 0) x axis (0, 0, 1)
  line L1 (186, 25.3346) -> (237, -63)
  line L2 (174, 25.3346) -> (186, 25.3346)
  line L3 (174, 0) -> (174, 25.3346)
  line L4 (0, 0) -> (174, 0)
  line L5 (0, 25.3346) -> (0, 0)
  line L6 (-12, 25.3346) -> (0, 25.3346)
  line L7 (-63, -63) -> (-12, 25.3346)
  line L8 (-13, -63) -> (-63, -63)
  line L9 (11.8261, -20) -> (-13, -63)
  line L10 (162.1739, -20) -> (11.8261, -20)
  line L11 (187, -63) -> (162.1739, -20)
  line L12 (237, -63) -> (187, -63)
  line L13 (-20.5, -63) -> (-55.5, -63)
  line L14 (-20.5, -75) -> (-20.5, -63)
  line L15 (-55.5, -75) -> (-20.5, -75)
  line L16 (-55.5, -63) -> (-55.5, -75)
  line L17 (87, -88.8512) -> (87, -20)
  line L18 (194.5, -63) -> (229.5, -63)
  line L19 (194.5, -75) -> (194.5, -63)
  line L20 (229.5, -63) -> (229.5, -75)
  line L21 (229.5, -75) -> (194.5, -75)
  point P14 (-55.5, -63)
  point P18 (87, -20)
  point P20 (229.5, -63)
  point P15 (-20.5, -63)
  point P21 (194.5, -63)
  point P16 (-20.5, -75)
  point P22 (194.5, -75)
  point P17 (-55.5, -75)
  point P23 (229.5, -75)
  point P9 (-63, -63)
  horizontal L13
  vertical L14
  horizontal L15
  vertical L16
  coincident L8 P14
  midpoint L10 P18
  perpendicular L10 L17
  symmetric P14 L17 P20
  symmetric P15 L17 P21
  symmetric P16 L17 P22
  symmetric P17 L17 P23
  dimension "d49" distance P9 P14 = 7.5
  dimension "d50" distance P16 P17 = 35
  dimension "d51" distance P15 P16 = 12
extrude "Extrude9" add sketch "finger joint" profile of L8 L12 L13 L14 L15 L16 L18 L19 L20 L21 against normal blind 12
sketch "finger joint (1)" plane through (462, 0, 0) normal (1, 0, 0) x axis (0, 0, -1)
  line L1 (-237, -63) -> (-186, 25.3346)
  line L2 (-187, -63) -> (-237, -63)
  line L3 (-162.1739, -20) -> (-187, -63)
  line L4 (-11.8261, -20) -> (-162.1739, -20)
  line L5 (13, -63) -> (-11.8261, -20)
  line L6 (63, -63) -> (13, -63)
  line L7 (12, 25.3346) -> (63, -63)
  line L8 (0, 25.3346) -> (12, 25.3346)
  line L9 (0, 0) -> (0, 25.3346)
  line L10 (-174, 0) -> (0, 0)
  line L11 (-174, 25.3346) -> (-174, 0)
  line L12 (-186, 25.3346) -> (-174, 25.3346)
  line L13 (-194.5, -63) -> (-229.5, -63)
  line L14 (-194.5, -75) -> (-194.5, -63)
  line L15 (-229.5, -75) -> (-194.5, -75)
  line L16 (-229.5, -63) -> (-229.5, -75)
  line L17 (-87, -73.3472) -> (-87, -20)
  line L18 (20.5, -63) -> (55.5, -63)
  line L19 (55.5, -63) -> (55.5, -75)
  line L20 (20.5, -75) -> (20.5, -63)
  line L21 (55.5, -75) -> (20.5, -75)
  point P14 (-229.5, -63)
  point P18 (-87, -20)
  point P20 (55.5, -63)
  point P15 (-194.5, -63)
  point P21 (20.5, -63)
  point P16 (-194.5, -75)
  point P23 (20.5, -75)
  point P17 (-229.5, -75)
  point P22 (55.5, -75)
  point P3 (-237, -63)
  horizontal L13
  vertical L14
  horizontal L15
  vertical L16
  coincident L2 P14
  midpoint L4 P18
  perpendicular L4 L17
  symmetric P14 L17 P20
  symmetric P15 L17 P21
  symmetric P16 L17 P23
  symmetric P17 L17 P22
  dimension "d54" distance P14 P17 = 12
  dimension "d55" distance P16 P17 = 35
  dimension "d56" distance P3 P14 = 7.5
extrude "Extrude10" add sketch "finger joint (1)" profile of L2 L6 L13 L14 L15 L16 L18 L19 L20 L21 against normal blind 12
work_plane "WorkPlane1" AlongDistance 75
sketch "Sketch10" plane through (0, -75, 0) normal (0, -1, 0) x axis (-1, 0, 0)
  line L1 (-600, -237) -> (100, -237)
  line L2 (-600, 63) -> (-600, -237)
  line L3 (100, 63) -> (-600, 63)
  line L4 (100, -237) -> (100, 63)
  line L5 (-462, -229.5) -> (-462, -194.5)
  line L6 (-450, -229.5) -> (-462, -229.5)
  line L7 (-450, -194.5) -> (-450, -229.5)
  line L8 (-462, -194.5) -> (-450, -194.5)
  line L9 (-462, 20.5) -> (-462, 55.5)
  line L10 (-450, 20.5) -> (-462, 20.5)
  line L11 (-450, 55.5) -> (-450, 20.5)
  line L12 (-462, 55.5) -> (-450, 55.5)
  line L13 (-50, 55.5) -> (-50, 20.5)
  line L14 (-62, 55.5) -> (-50, 55.5)
  line L15 (-62, 20.5) -> (-62, 55.5)
  line L16 (-50, 20.5) -> (-62, 20.5)
  line L17 (-50, -194.5) -> (-50, -229.5)
  line L18 (-62, -194.5) -> (-50, -194.5)
  line L19 (-62, -229.5) -> (-62, -194.5)
  line L20 (-50, -229.5) -> (-62, -229.5)
  point P6 (-62, 63)
  point P2 (100, -237)
  point P3 (-600, -237)
  point P5 (100, 63)
  horizontal L1
  vertical L2
  horizontal L3
  vertical L4
  coincident L3 P6
  dimension "d60" distance P2 P3 = 700
  dimension "d62" distance P2 P5 = 300
extrude "Extrude11" new body sketch "Sketch10" against normal blind 12 bodies "platform"
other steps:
base_feature "Base Feature" bodies "Stand legs2"
named bodies: "Front", "Top", "Bottom", "Back", "window", "Stand legs1", "Stand legs2", "platform"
